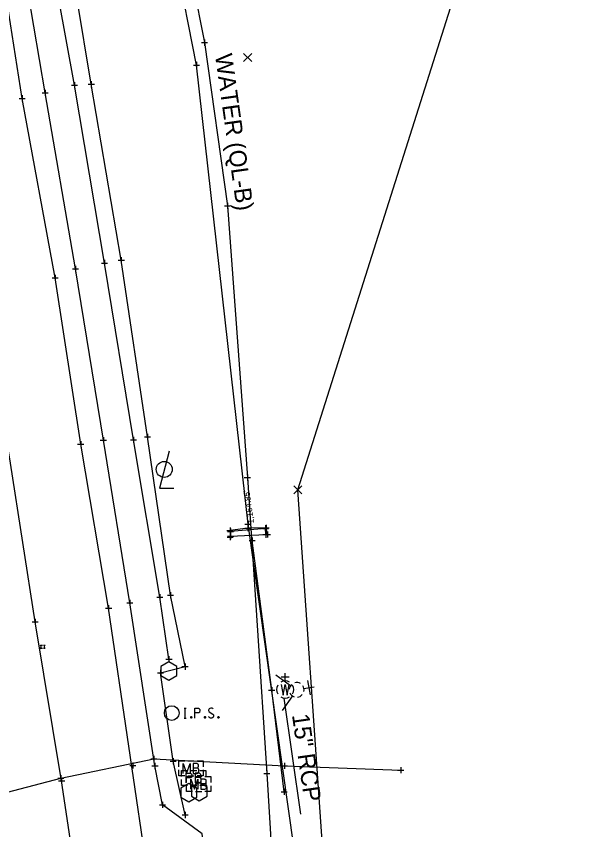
# Model space of a CAD drawing. Extents: x 2324380 to 2325559, y 691096 to 693386.
# Drawn here: x 2325179.7 to 2325270.8, y 691658.5 to 691791.1 of the extents above; entities that cross this region are included whole.
import ezdxf

# ---------------------------------------------------------------- set-up
doc = ezdxf.new("R2010")
doc.units = 0
for name, color, linetype in [('DR_X_Elev_Flow', 7, 'Continuous'), ('DR_X_Headwall', 7, 'Continuous'), ('DR_X_Storm_Sewer', 7, 'Continuous'), ('DR_X_Text', 7, 'Continuous'), ('LT_X_Poles', 7, 'Continuous'), ('PM_X_Cells', 7, 'Continuous'), ('PM_X_CL_Double_Solid', 7, 'Continuous'), ('PM_X_Transverse_Line', 7, 'Continuous'), ('PV_X_COP', 7, 'Continuous'), ('PV_X_EOP', 7, 'Continuous'), ('PV_X_Shoulder_Aggregate', 7, 'Continuous'), ('RD_X_Cells', 7, 'Continuous'), ('RD_X_GR_Rt', 7, 'Continuous'), ('SC_Scratch1', 7, 'Continuous'), ('SV_P_Mon_Cells_Set', 7, 'Continuous'), ('SV_X_Break_Lines', 7, 'Continuous'), ('SV_X_Random_Point', 7, 'Continuous'), ('SV_X_Shot_Marker', 7, 'Continuous'), ('SV_X_Terrain_Boundary', 7, 'Continuous'), ('SV_X_Toe_of_Slope', 7, 'Continuous'), ('UT_X_Gas', 7, 'Continuous'), ('UT_X_Water', 7, 'Continuous'), ('UT_X_Water_Cells', 7, 'Continuous'), ('UT_X_Water_Text', 7, 'Continuous')]:
    doc.layers.add(name, color=color, linetype=linetype)

msp = doc.modelspace()

# ---------------------------------------------------------------- linework, layer by layer
at = {"layer": 'DR_X_Elev_Flow'}
for p, q in [((2325217.02, 691708.33), (2325218.02, 691708.33)), ((2325217.52, 691708.83), (2325217.52, 691707.83)), ((2325217.52, 691708.33), (2325217.52, 691708.33))]:
    msp.add_line(p, q, dxfattribs=at)
at = {"layer": 'DR_X_Headwall'}
msp.add_lwpolyline([(2325214.67, 691707.11), (2325214.68, 691706.37), (2325220.41, 691706.6), (2325220.36, 691707.63)], close=True, dxfattribs=at)
at = {"layer": 'DR_X_Storm_Sewer'}
msp.add_line((2325229.09, 691626.77), (2325217.52, 691708.33), dxfattribs=at)
at = {"layer": 'DR_X_Text'}
msp.add_line((2325223.38, 691679.92), (2325226.06, 691661.02), dxfattribs=at)
at = {"layer": 'LT_X_Poles'}
msp.add_lwpolyline([(2325204.63, 691720.19), (2325203.06, 691714.2), (2325205.42, 691714.2)], dxfattribs=at)
msp.add_circle((2325203.85, 691717.24), 1.3, dxfattribs=at)
at = {"layer": 'PM_X_Cells'}
for p, q in [((2325183.63, 691688.58), (2325183.73, 691688.58)), ((2325183.63, 691688.09), (2325183.73, 691688.09)), ((2325183.79, 691688.58), (2325183.89, 691688.58)), ((2325183.79, 691688.09), (2325183.89, 691688.09)), ((2325183.96, 691688.58), (2325184.06, 691688.58)), ((2325183.96, 691688.09), (2325184.06, 691688.09)), ((2325184.01, 691688.33), (2325184.01, 691688.33)), ((2325184.13, 691688.58), (2325184.23, 691688.58)), ((2325184.13, 691688.09), (2325184.23, 691688.09)), ((2325184.3, 691688.58), (2325184.4, 691688.58)), ((2325184.3, 691688.09), (2325184.4, 691688.09))]:
    msp.add_line(p, q, dxfattribs=at)
for centre, start, end in [((2325183.47, 691688.33), 42.0847, 58.0262), ((2325183.47, 691688.33), 301.9738, 317.9205), ((2325183.47, 691688.33), 18.8878, 34.8207), ((2325183.47, 691688.33), 325.1782, 341.1111), ((2325183.47, 691688.33), 348.3904, 11.6202), ((2325184.55, 691688.33), 168.3816, 191.6091), ((2325184.55, 691688.33), 145.1782, 161.1098), ((2325184.55, 691688.33), 198.8872, 214.8207), ((2325184.55, 691688.33), 121.9738, 137.9163), ((2325184.55, 691688.33), 222.0817, 238.0262)]:
    msp.add_arc(centre, 0.288, start, end, dxfattribs=at)
at = {"layer": 'PM_X_CL_Double_Solid'}
msp.add_lwpolyline([(2325203.69, 691549.65), (2325199.81, 691578.72), (2325195.9, 691603.62), (2325192.28, 691631.74), (2325187.11, 691666.48), (2325182.79, 691692.39), (2325178.74, 691718.23), (2325173.96, 691747.27), (2325169.08, 691775.55), (2325163.39, 691807.62), (2325158.37, 691834.22), (2325153.07, 691860.53), (2325147.82, 691885.48), (2325142.33, 691910.37), (2325135.95, 691937.62), (2325128.86, 691967.59), (2325122.12, 691994.31), (2325114.33, 692023.68), (2325108.45, 692046.03), (2325104.94, 692058.15)], dxfattribs=at)
at = {"layer": 'PM_X_Transverse_Line'}
msp.add_lwpolyline([(2325208.03, 691604.62), (2325194.77, 691694.59), (2325190.22, 691721.35), (2325186.04, 691748.47), (2325180.66, 691777.72), (2325175.44, 691810.81), (2325170.12, 691836.61), (2325164.91, 691862.73), (2325159.59, 691887.99), (2325154.32, 691913.69), (2325148, 691940.38), (2325141.01, 691970.75), (2325134.25, 691997.6), (2325126.61, 692026.24), (2325119.99, 692049.57), (2325112.24, 692077.64)], dxfattribs=at)
at = {"layer": 'PV_X_COP'}
msp.add_lwpolyline([(2325203.69, 691549.65), (2325199.81, 691578.72), (2325195.9, 691603.62), (2325192.28, 691631.74), (2325187.11, 691666.48), (2325182.79, 691692.39), (2325178.74, 691718.23), (2325173.96, 691747.27), (2325169.08, 691775.55), (2325163.39, 691807.62), (2325158.37, 691834.22), (2325153.07, 691860.53), (2325147.82, 691885.48), (2325142.33, 691910.37), (2325135.95, 691937.62), (2325128.86, 691967.59), (2325122.12, 691994.31), (2325114.33, 692023.68), (2325108.45, 692046.03), (2325099.34, 692075.66)], dxfattribs=at)
at = {"layer": 'PV_X_EOP'}
msp.add_lwpolyline([(2325211.92, 691605.39), (2325210.37, 691618.55), (2325213.96, 691624.8), (2325210.03, 691657.83), (2325203.56, 691662.57), (2325202.33, 691668.93), (2325198.24, 691695.48), (2325193.91, 691721.99), (2325189.38, 691749.91), (2325184.43, 691778.63), (2325178.88, 691811.26), (2325173.94, 691837.31), (2325168.71, 691863.96), (2325163.82, 691888.36), (2325158.39, 691913.65), (2325152.29, 691941.35), (2325145.12, 691971.33), (2325138.19, 691997.21), (2325140.74, 692005.58), (2325134.93, 692029.17), (2325130.4, 692046.73), (2325123.25, 692051.46), (2325115.82, 692078.51)], dxfattribs=at)
at = {"layer": 'PV_X_Shoulder_Aggregate'}
for p, q in [((2325191.94, 691780.01), (2325186.6, 691812.23)), ((2325196.84, 691751.36), (2325191.94, 691780.01)), ((2325201.1, 691722.54), (2325196.84, 691751.36)), ((2325204.86, 691696.74), (2325201.1, 691722.54)), ((2325207.24, 691685.08), (2325204.86, 691696.74)), ((2325203.23, 691684.05), (2325207.24, 691685.08)), ((2325205.3, 691669.69), (2325203.23, 691684.05)), ((2325207.25, 691660.91), (2325205.3, 691669.69))]:
    msp.add_line(p, q, dxfattribs=at)
at = {"layer": 'RD_X_Cells'}
for p, q in [((2325207.7, 691669.71), (2325208.7, 691669.71)), ((2325208.14, 691668.14), (2325209.14, 691668.14)), ((2325208.21, 691668.49), (2325208.21, 691668.49)), ((2325207.7, 691667.27), (2325208.7, 691667.27)), ((2325208.65, 691666.92), (2325208.65, 691666.92)), ((2325208.96, 691667.15), (2325209.96, 691667.15)), ((2325208.14, 691665.7), (2325209.14, 691665.7)), ((2325209.47, 691665.93), (2325209.47, 691665.93)), ((2325208.96, 691664.71), (2325209.96, 691664.71))]:
    msp.add_line(p, q, dxfattribs=at)
for points in [[(2325203.3, 691683.63), (2325204.6, 691682.88), (2325205.9, 691683.63), (2325205.9, 691685.13), (2325204.6, 691685.88), (2325203.3, 691685.13), (2325203.3, 691683.63)], [(2325206.21, 691668.74), (2325206.21, 691669.71), (2325207.18, 691669.71)], [(2325209.21, 691669.71), (2325210.21, 691669.71), (2325210.21, 691668.74)], [(2325207.18, 691667.27), (2325206.21, 691667.27), (2325206.21, 691668.24)], [(2325206.65, 691667.17), (2325206.65, 691668.14), (2325207.62, 691668.14)], [(2325206.91, 691667.69), (2325206.91, 691669.29), (2325207.49, 691667.69), (2325208.05, 691669.29), (2325208.05, 691667.69)], [(2325209.23, 691668.56), (2325209.29, 691668.62), (2325209.33, 691668.66), (2325209.36, 691668.7), (2325209.37, 691668.72), (2325209.39, 691668.77), (2325209.41, 691668.81), (2325209.43, 691668.9), (2325209.43, 691668.94), (2325209.43, 691668.99), (2325209.42, 691669.06), (2325209.39, 691669.13), (2325209.36, 691669.18), (2325209.29, 691669.23), (2325209.24, 691669.25), (2325209.22, 691669.27), (2325209.15, 691669.29), (2325208.54, 691669.29), (2325208.54, 691667.69), (2325209.23, 691667.69), (2325209.32, 691667.74), (2325209.39, 691667.8), (2325209.46, 691667.91), (2325209.49, 691668.02), (2325209.51, 691668.13), (2325209.51, 691668.21), (2325209.48, 691668.28), (2325209.43, 691668.4), (2325209.37, 691668.47), (2325209.23, 691668.56), (2325208.54, 691668.56)], [(2325210.21, 691668.24), (2325210.21, 691667.27), (2325209.21, 691667.27)], [(2325209.65, 691668.14), (2325210.65, 691668.14), (2325210.65, 691667.17)], [(2325207.42, 691666.12), (2325207.42, 691667.72), (2325208.03, 691667.72), (2325208.09, 691667.71), (2325208.18, 691667.69), (2325208.21, 691667.66), (2325208.25, 691667.64), (2325208.3, 691667.57), (2325208.34, 691667.51), (2325208.37, 691667.41), (2325208.37, 691667.26), (2325208.35, 691667.21), (2325208.33, 691667.13), (2325208.28, 691667.04), (2325208.23, 691667.01), (2325208.19, 691666.98), (2325208.13, 691666.95), (2325208.03, 691666.94), (2325207.42, 691666.94)], [(2325207.47, 691666.18), (2325207.47, 691667.15), (2325208.44, 691667.15)], [(2325209.6, 691666.99), (2325209.66, 691667.06), (2325209.7, 691667.09), (2325209.73, 691667.13), (2325209.74, 691667.16), (2325209.76, 691667.21), (2325209.78, 691667.24), (2325209.8, 691667.33), (2325209.8, 691667.37), (2325209.8, 691667.42), (2325209.79, 691667.5), (2325209.76, 691667.56), (2325209.73, 691667.61), (2325209.66, 691667.66), (2325209.61, 691667.69), (2325209.59, 691667.7), (2325209.52, 691667.72), (2325208.91, 691667.72), (2325208.91, 691666.12), (2325209.6, 691666.12), (2325209.69, 691666.17), (2325209.76, 691666.24), (2325209.83, 691666.34), (2325209.86, 691666.45), (2325209.88, 691666.56), (2325209.88, 691666.64), (2325209.85, 691666.72), (2325209.8, 691666.83), (2325209.74, 691666.9), (2325209.6, 691666.99), (2325208.91, 691666.99)], [(2325210.48, 691667.15), (2325211.47, 691667.15), (2325211.47, 691666.18)], [(2325206.55, 691663.79), (2325207.84, 691663.04), (2325209.14, 691663.79), (2325209.14, 691665.29), (2325207.84, 691666.04), (2325206.55, 691665.29), (2325206.55, 691663.79)], [(2325207.62, 691665.7), (2325206.65, 691665.7), (2325206.65, 691666.67)], [(2325208.44, 691664.71), (2325207.47, 691664.71), (2325207.47, 691665.68)], [(2325208.18, 691665.13), (2325208.18, 691666.73), (2325208.76, 691665.13), (2325209.31, 691666.73), (2325209.31, 691665.13)], [(2325208.27, 691663.95), (2325209.57, 691663.2), (2325210.87, 691663.95), (2325210.87, 691665.45), (2325209.57, 691666.2), (2325208.27, 691665.45), (2325208.27, 691663.95)], [(2325210.65, 691666.67), (2325210.65, 691665.7), (2325209.65, 691665.7)], [(2325210.49, 691666), (2325210.56, 691666.06), (2325210.6, 691666.1), (2325210.62, 691666.14), (2325210.63, 691666.16), (2325210.66, 691666.21), (2325210.67, 691666.25), (2325210.7, 691666.34), (2325210.7, 691666.38), (2325210.7, 691666.43), (2325210.68, 691666.5), (2325210.66, 691666.56), (2325210.62, 691666.61), (2325210.56, 691666.67), (2325210.51, 691666.69), (2325210.48, 691666.7), (2325210.42, 691666.73), (2325209.8, 691666.73), (2325209.8, 691665.13), (2325210.49, 691665.13), (2325210.58, 691665.18), (2325210.66, 691665.24), (2325210.72, 691665.34), (2325210.76, 691665.46), (2325210.77, 691665.57), (2325210.77, 691665.64), (2325210.75, 691665.72), (2325210.7, 691665.83), (2325210.63, 691665.91), (2325210.49, 691666), (2325209.8, 691666)], [(2325211.47, 691665.68), (2325211.47, 691664.71), (2325210.48, 691664.71)]]:
    msp.add_lwpolyline(points, dxfattribs=at)
at = {"layer": 'RD_X_GR_Rt'}
for p, q in [((2325189.2, 691779.88), (2325183.38, 691811.73)), ((2325194.09, 691750.88), (2325189.2, 691779.88)), ((2325198.83, 691722.06), (2325194.09, 691750.88)), ((2325203.12, 691696.4), (2325198.83, 691722.06)), ((2325204.62, 691686.3), (2325203.12, 691696.4))]:
    msp.add_line(p, q, dxfattribs=at)
at = {"layer": 'SV_P_Mon_Cells_Set'}
for points in [[(2325207.09, 691678.31), (2325207.44, 691678.31)], [(2325207.27, 691676.71), (2325207.27, 691678.31)], [(2325208.83, 691676.71), (2325208.83, 691678.31), (2325209.36, 691678.31), (2325209.41, 691678.3), (2325209.49, 691678.27), (2325209.53, 691678.25), (2325209.56, 691678.22), (2325209.6, 691678.16), (2325209.64, 691678.1), (2325209.66, 691678), (2325209.66, 691677.85), (2325209.65, 691677.8), (2325209.62, 691677.72), (2325209.58, 691677.63), (2325209.54, 691677.59), (2325209.5, 691677.57), (2325209.45, 691677.54), (2325209.36, 691677.53), (2325208.83, 691677.53)], [(2325211.84, 691678.2), (2325211.82, 691678.22), (2325211.78, 691678.25), (2325211.69, 691678.29), (2325211.56, 691678.31), (2325211.48, 691678.31), (2325211.44, 691678.31), (2325211.3, 691678.27), (2325211.18, 691678.2), (2325211.1, 691678.1), (2325211.08, 691678), (2325211.08, 691677.92), (2325211.1, 691677.82), (2325211.19, 691677.73), (2325211.8, 691677.36), (2325211.85, 691677.3), (2325211.87, 691677.25), (2325211.89, 691677.18), (2325211.89, 691677.1), (2325211.88, 691677.03), (2325211.87, 691676.98), (2325211.85, 691676.91), (2325211.83, 691676.86), (2325211.81, 691676.83), (2325211.77, 691676.79), (2325211.74, 691676.76), (2325211.7, 691676.74), (2325211.66, 691676.73), (2325211.56, 691676.71), (2325211.41, 691676.71), (2325211.31, 691676.74), (2325211.17, 691676.83), (2325211.08, 691676.9)], [(2325207.09, 691676.71), (2325207.44, 691676.71)], [(2325208.22, 691676.93), (2325208.28, 691676.93), (2325208.31, 691676.9), (2325208.35, 691676.85), (2325208.35, 691676.79), (2325208.31, 691676.74), (2325208.28, 691676.71), (2325208.22, 691676.71), (2325208.19, 691676.74), (2325208.16, 691676.79), (2325208.16, 691676.85), (2325208.19, 691676.9), (2325208.22, 691676.93)], [(2325210.47, 691676.93), (2325210.53, 691676.93), (2325210.56, 691676.9), (2325210.59, 691676.85), (2325210.59, 691676.79), (2325210.56, 691676.74), (2325210.53, 691676.71), (2325210.47, 691676.71), (2325210.44, 691676.74), (2325210.41, 691676.79), (2325210.41, 691676.85), (2325210.44, 691676.9), (2325210.47, 691676.93)], [(2325212.66, 691676.93), (2325212.71, 691676.93), (2325212.74, 691676.9), (2325212.78, 691676.85), (2325212.78, 691676.79), (2325212.74, 691676.74), (2325212.71, 691676.71), (2325212.66, 691676.71), (2325212.62, 691676.74), (2325212.59, 691676.79), (2325212.59, 691676.85), (2325212.62, 691676.9), (2325212.66, 691676.93)]]:
    msp.add_lwpolyline(points, dxfattribs=at)
msp.add_circle((2325205.07, 691677.51), 1.2, dxfattribs=at)
at = {"layer": 'SV_X_Break_Lines'}
msp.add_lwpolyline([(2325220.7, 691706.64), (2325220.49, 691707.71), (2325217.47, 691707.65), (2325214.58, 691707.29), (2325214.59, 691706.21)], dxfattribs=at)
at = {"layer": 'SV_X_Random_Point'}
for p, q in [((2325216.78, 691783.71), (2325218.11, 691785.04)), ((2325216.78, 691785.04), (2325218.11, 691783.71)), ((2325224.97, 691713.23), (2325226.3, 691714.56)), ((2325224.97, 691714.56), (2325226.3, 691713.23))]:
    msp.add_line(p, q, dxfattribs=at)
at = {"layer": 'SV_X_Shot_Marker'}
for p, q in [((2325209.93, 691786.81), (2325210.93, 691786.81)), ((2325210.43, 691787.31), (2325210.43, 691786.31)), ((2325210.43, 691786.81), (2325210.43, 691786.81)), ((2325209.12, 691783.66), (2325209.12, 691782.66)), ((2325208.62, 691783.16), (2325209.62, 691783.16)), ((2325209.12, 691783.16), (2325209.12, 691783.16)), ((2325188.7, 691779.88), (2325189.7, 691779.88)), ((2325189.2, 691780.38), (2325189.2, 691779.38)), ((2325189.2, 691779.88), (2325189.2, 691779.88)), ((2325191.44, 691780.01), (2325192.44, 691780.01)), ((2325191.94, 691780.51), (2325191.94, 691779.51)), ((2325191.94, 691780.01), (2325191.94, 691780.01)), ((2325180.66, 691778.22), (2325180.66, 691777.22)), ((2325183.93, 691778.63), (2325184.93, 691778.63)), ((2325184.43, 691779.13), (2325184.43, 691778.13)), ((2325184.43, 691778.63), (2325184.43, 691778.63)), ((2325180.16, 691777.72), (2325181.16, 691777.72)), ((2325180.66, 691777.72), (2325180.66, 691777.72)), ((2325213.65, 691760.19), (2325214.65, 691760.19)), ((2325214.15, 691760.69), (2325214.15, 691759.69)), ((2325214.15, 691760.19), (2325214.15, 691760.19)), ((2325196.84, 691751.86), (2325196.84, 691750.86)), ((2325189.38, 691750.41), (2325189.38, 691749.41)), ((2325193.59, 691750.88), (2325194.59, 691750.88)), ((2325194.09, 691751.38), (2325194.09, 691750.38)), ((2325194.09, 691750.88), (2325194.09, 691750.88)), ((2325196.34, 691751.36), (2325197.34, 691751.36)), ((2325196.84, 691751.36), (2325196.84, 691751.36)), ((2325188.88, 691749.91), (2325189.88, 691749.91)), ((2325189.38, 691749.91), (2325189.38, 691749.91)), ((2325185.54, 691748.47), (2325186.54, 691748.47)), ((2325186.04, 691748.97), (2325186.04, 691747.97)), ((2325186.04, 691748.47), (2325186.04, 691748.47)), ((2325193.91, 691722.49), (2325193.91, 691721.49)), ((2325198.83, 691722.56), (2325198.83, 691721.56)), ((2325200.6, 691722.54), (2325201.6, 691722.54)), ((2325201.1, 691723.04), (2325201.1, 691722.04)), ((2325201.1, 691722.54), (2325201.1, 691722.54)), ((2325189.72, 691721.35), (2325190.72, 691721.35)), ((2325190.22, 691721.85), (2325190.22, 691720.85)), ((2325190.22, 691721.35), (2325190.22, 691721.35)), ((2325193.41, 691721.99), (2325194.41, 691721.99)), ((2325193.91, 691721.99), (2325193.91, 691721.99)), ((2325198.33, 691722.06), (2325199.33, 691722.06)), ((2325198.83, 691722.06), (2325198.83, 691722.06)), ((2325216.91, 691715.9), (2325217.91, 691715.9)), ((2325217.41, 691716.4), (2325217.41, 691715.4)), ((2325217.41, 691715.9), (2325217.41, 691715.9)), ((2325217.05, 691708.33), (2325218.05, 691708.33)), ((2325217.47, 691708.15), (2325217.47, 691707.15)), ((2325217.55, 691708.83), (2325217.55, 691707.83)), ((2325217.55, 691708.33), (2325217.55, 691708.33)), ((2325220.36, 691708.13), (2325220.36, 691707.13)), ((2325220.49, 691708.21), (2325220.49, 691707.21)), ((2325214.08, 691707.29), (2325215.08, 691707.29)), ((2325214.17, 691707.11), (2325215.17, 691707.11)), ((2325214.58, 691707.79), (2325214.58, 691706.79)), ((2325214.58, 691707.29), (2325214.58, 691707.29)), ((2325214.59, 691706.71), (2325214.59, 691705.71)), ((2325214.67, 691707.61), (2325214.67, 691706.61)), ((2325214.67, 691707.11), (2325214.67, 691707.11)), ((2325214.68, 691706.87), (2325214.68, 691705.87)), ((2325216.97, 691707.65), (2325217.97, 691707.65)), ((2325217.47, 691707.65), (2325217.47, 691707.65)), ((2325219.86, 691707.63), (2325220.86, 691707.63)), ((2325219.91, 691706.6), (2325220.91, 691706.6)), ((2325219.99, 691707.71), (2325220.99, 691707.71)), ((2325220.2, 691706.64), (2325221.2, 691706.64)), ((2325220.36, 691707.63), (2325220.36, 691707.63)), ((2325220.41, 691707.1), (2325220.41, 691706.1)), ((2325220.41, 691706.6), (2325220.41, 691706.6)), ((2325220.49, 691707.71), (2325220.49, 691707.71)), ((2325220.7, 691707.14), (2325220.7, 691706.14)), ((2325220.7, 691706.64), (2325220.7, 691706.64)), ((2325214.09, 691706.21), (2325215.09, 691706.21)), ((2325214.18, 691706.37), (2325215.18, 691706.37)), ((2325214.59, 691706.21), (2325214.59, 691706.21)), ((2325214.68, 691706.37), (2325214.68, 691706.37)), ((2325217.69, 691705.65), (2325218.69, 691705.65)), ((2325218.19, 691706.15), (2325218.19, 691705.15)), ((2325218.19, 691705.65), (2325218.19, 691705.65)), ((2325198.24, 691695.98), (2325198.24, 691694.98)), ((2325202.62, 691696.4), (2325203.62, 691696.4)), ((2325203.12, 691696.9), (2325203.12, 691695.9)), ((2325203.12, 691696.4), (2325203.12, 691696.4)), ((2325204.36, 691696.74), (2325205.36, 691696.74)), ((2325204.86, 691697.24), (2325204.86, 691696.24)), ((2325204.86, 691696.74), (2325204.86, 691696.74)), ((2325194.77, 691695.09), (2325194.77, 691694.09)), ((2325197.74, 691695.48), (2325198.74, 691695.48)), ((2325198.24, 691695.48), (2325198.24, 691695.48)), ((2325194.27, 691694.59), (2325195.27, 691694.59)), ((2325194.77, 691694.59), (2325194.77, 691694.59)), ((2325182.29, 691692.39), (2325183.29, 691692.39)), ((2325182.29, 691692.39), (2325183.29, 691692.39)), ((2325182.79, 691692.89), (2325182.79, 691691.89)), ((2325182.79, 691692.89), (2325182.79, 691691.89)), ((2325182.79, 691692.39), (2325182.79, 691692.39)), ((2325182.79, 691692.39), (2325182.79, 691692.39)), ((2325204.62, 691686.8), (2325204.62, 691685.8)), ((2325204.12, 691686.3), (2325205.12, 691686.3)), ((2325204.62, 691686.3), (2325204.62, 691686.3)), ((2325207.24, 691685.58), (2325207.24, 691684.58)), ((2325202.73, 691684.05), (2325203.73, 691684.05)), ((2325203.23, 691684.55), (2325203.23, 691683.55)), ((2325203.23, 691684.05), (2325203.23, 691684.05)), ((2325206.74, 691685.08), (2325207.74, 691685.08)), ((2325207.24, 691685.08), (2325207.24, 691685.08)), ((2325221.38, 691681.74), (2325221.38, 691680.74)), ((2325220.88, 691681.24), (2325221.88, 691681.24)), ((2325221.38, 691681.24), (2325221.38, 691681.24)), ((2325198.72, 691669.46), (2325198.72, 691668.46)), ((2325201.64, 691670.03), (2325202.64, 691670.03)), ((2325202.14, 691670.53), (2325202.14, 691669.53)), ((2325202.14, 691670.03), (2325202.14, 691670.03)), ((2325202.33, 691669.43), (2325202.33, 691668.43)), ((2325204.8, 691669.69), (2325205.8, 691669.69)), ((2325205.3, 691670.19), (2325205.3, 691669.19)), ((2325205.3, 691669.69), (2325205.3, 691669.69)), ((2325223.47, 691669.42), (2325223.47, 691668.42)), ((2325198.22, 691668.96), (2325199.22, 691668.96)), ((2325198.72, 691668.96), (2325198.72, 691668.96)), ((2325201.83, 691668.93), (2325202.83, 691668.93)), ((2325202.33, 691668.93), (2325202.33, 691668.93)), ((2325220.6, 691668.17), (2325220.6, 691667.17)), ((2325222.97, 691668.92), (2325223.97, 691668.92)), ((2325223.47, 691668.92), (2325223.47, 691668.92)), ((2325241.93, 691668.22), (2325242.93, 691668.22)), ((2325242.43, 691668.72), (2325242.43, 691667.72)), ((2325242.43, 691668.22), (2325242.43, 691668.22)), ((2325186.49, 691666.9), (2325187.49, 691666.9)), ((2325186.99, 691667.4), (2325186.99, 691666.4)), ((2325186.99, 691666.9), (2325186.99, 691666.9)), ((2325187.11, 691666.98), (2325187.11, 691665.98)), ((2325187.11, 691666.98), (2325187.11, 691665.98)), ((2325220.1, 691667.67), (2325221.1, 691667.67)), ((2325220.6, 691667.67), (2325220.6, 691667.67)), ((2325186.61, 691666.48), (2325187.61, 691666.48)), ((2325186.61, 691666.48), (2325187.61, 691666.48)), ((2325187.11, 691666.48), (2325187.11, 691666.48)), ((2325187.11, 691666.48), (2325187.11, 691666.48)), ((2325222.91, 691664.68), (2325223.91, 691664.68)), ((2325223.41, 691665.18), (2325223.41, 691664.18)), ((2325223.41, 691664.68), (2325223.41, 691664.68)), ((2325203.56, 691663.07), (2325203.56, 691662.07)), ((2325203.06, 691662.57), (2325204.06, 691662.57)), ((2325203.56, 691662.57), (2325203.56, 691662.57)), ((2325206.75, 691660.91), (2325207.75, 691660.91)), ((2325207.25, 691661.41), (2325207.25, 691660.41)), ((2325207.25, 691660.91), (2325207.25, 691660.91))]:
    msp.add_line(p, q, dxfattribs=at)
at = {"layer": 'SV_X_Terrain_Boundary'}
msp.add_lwpolyline([(2325246.03, 691497.72), (2325238.21, 691553.54), (2325237.01, 691616.17), (2325236.06, 691624.28), (2325229.73, 691655.12), (2325225.64, 691713.9), (2325265.08, 691838.33), (2325358.67, 691858.64)], dxfattribs=at)
at = {"layer": 'SV_X_Toe_of_Slope'}
for points in [[(2325217.55, 691708.33), (2325209.12, 691783.16), (2325199.14, 691833.73), (2325229.59, 691840.86), (2325259.98, 691849.99)], [(2325223.41, 691664.68), (2325221.38, 691681.24), (2325218.19, 691705.65)]]:
    msp.add_lwpolyline(points, dxfattribs=at)
at = {"layer": 'UT_X_Gas'}
msp.add_lwpolyline([(2325157.27, 691659.16), (2325186.99, 691666.9), (2325202.14, 691670.03), (2325223.47, 691668.92), (2325242.43, 691668.22)], dxfattribs=at)
at = {"layer": 'UT_X_Water'}
msp.add_lwpolyline([(2325124.52, 692091.67), (2325134.64, 692057.74), (2325147.68, 692015.89), (2325157.51, 691980.18), (2325171.32, 691933.62), (2325182.7, 691894.58), (2325195.31, 691848.43), (2325206.62, 691806.01), (2325210.43, 691786.81), (2325214.15, 691760.19), (2325217.41, 691715.9), (2325220.6, 691667.67), (2325222.98, 691628.17), (2325224.5, 691603.22), (2325224.97, 691587.75)], dxfattribs=at)
at = {"layer": 'UT_X_Water_Cells'}
for p, q in [((2325223.58, 691682.75), (2325223.58, 691684.02)), ((2325224.47, 691681.98), (2325222.06, 691683.67)), ((2325224.21, 691683.39), (2325222.94, 691683.39)), ((2325227.69, 691680.47), (2325227.27, 691682.84)), ((2325226.63, 691681.5), (2325228.33, 691681.8)), ((2325224.76, 691680.32), (2325223.07, 691677.91)), ((2325223.58, 691681.35), (2325223.58, 691681.35)), ((2325225.45, 691681.3), (2325225.45, 691681.3)), ((2325225.45, 691681.3), (2325225.45, 691681.3))]:
    msp.add_line(p, q, dxfattribs=at)
msp.add_lwpolyline([(2325222.94, 691682.17), (2325223.26, 691680.45), (2325223.58, 691682.17), (2325223.9, 691680.45), (2325224.21, 691682.17)], dxfattribs=at)
for centre, radius, start, end in [((2325223.58, 691681.35), 1.4, 60.0184, 120.0157), ((2325223.58, 691681.35), 1.4, 150.0184, 209.9816), ((2325225.45, 691681.3), 1.2, 131.8255, 175.7946), ((2325223.58, 691681.35), 1.4, 330.0184, 29.9816), ((2325225.45, 691681.3), 1.2, 59.9677, 104.0096), ((2325225.45, 691681.3), 1.2, 348.0861, 31.9847), ((2325223.58, 691681.35), 1.4, 239.9843, 299.9816), ((2325225.45, 691681.3), 1.2, 203.7706, 249.8564), ((2325225.45, 691681.3), 1.2, 275.9632, 319.9355)]:
    msp.add_arc(centre, radius, start, end, dxfattribs=at)

# ---------------------------------------------------------------- texts
at = {"layer": 'DR_X_Text'}
msp.add_text('15" RCP', height=2.8, rotation=278.0692, dxfattribs=at).set_placement((2325224.68, 691677.21))
at = {"layer": 'SC_Scratch1'}
msp.add_text("1,164.85'", height=1, rotation=98.0692, dxfattribs=at).set_placement((2325218.51, 691708.47))
at = {"layer": 'UT_X_Water_Text'}
msp.add_text('WATER (QL-B)', height=2.8, rotation=277.9604, dxfattribs=at).set_placement((2325212.12, 691784.8))

doc.saveas('drawing.dxf')
